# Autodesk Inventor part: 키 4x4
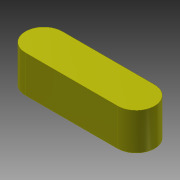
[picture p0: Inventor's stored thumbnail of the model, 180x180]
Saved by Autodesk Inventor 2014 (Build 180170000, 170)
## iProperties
Created: 2016-04
Part Number: 키 4x4
Document SubType Name: Modeling
Designer: mdu
Density: 7.86 g/cm^3
Mass: 1.65269 g
Surface Area: 2.35398 cm^2
Volume: 0.210265 cm^3
Material: 강철, 연강
Appearance: 노란색
Author: mdu
Revision Number: 1
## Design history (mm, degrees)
sketch "스케치1"
  geometry: L1 (-5, -2)-(5, -2); L2 (5, 2)-(-5, 2); A1 r 2 centre (5, 0) between (5, -2) and (5, 2); A2 r 2 centre (-5, 0) between (-5, 2) and (-5, -2); 2 further points
  constraints: 4 end point, 4 point on circle, 4 tangent, 2 centre point, 1 horizontal, 1 horizontal alignment, 1 midpoint, 1 parallel, 1 vertical alignment
  dimensions: "d0" = 4 distance between parallel lines of L1 L2; "d1" = 14 dimension on A1 A2
extrude "돌출1" new body sketch "스케치1" stored distance "d2" = 4; taper "d3" = 0 deg
chamfer "모따기1" distance "d4" = 0.5; stored, may be unused: second distance "d5" = 2, angle "d6" = 45 deg
node "솔리드1"
other parameters: "d0" = 4
